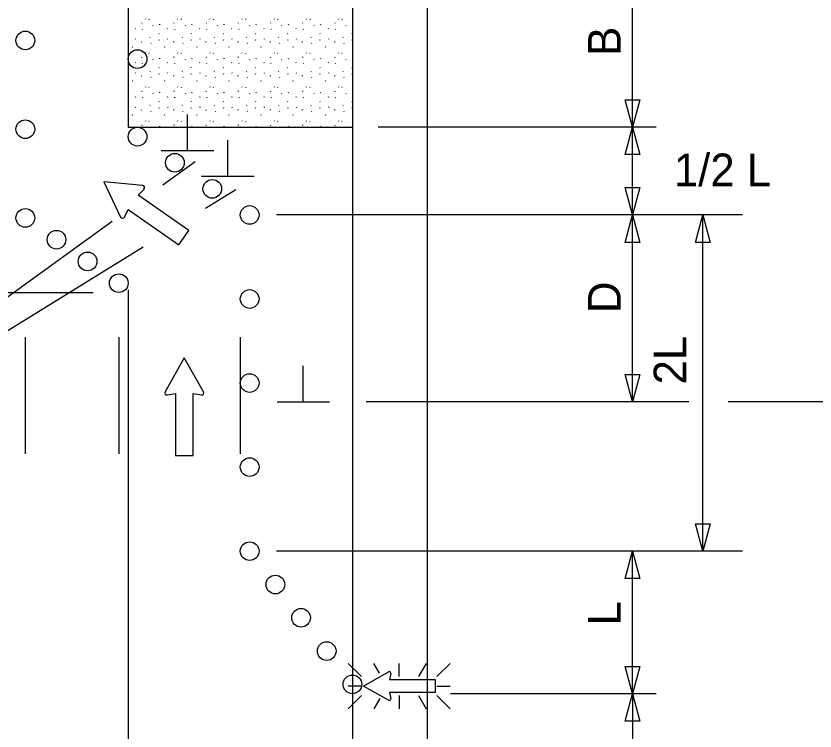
# Model space of a CAD drawing. Extents: x 16525 to 18478, y 5730 to 6927.
# Drawn here: x 17075.6 to 17246.6, y 6369.8 to 6523 of the extents above; entities that cross this region are included whole.
import ezdxf

# ---------------------------------------------------------------- set-up
doc = ezdxf.new("R2010")
doc.units = 0
for name, color, linetype in [('ALI_LEGAL_EX', 7, 'Continuous'), ('MT_SCRATCH_LEVEL_A', 7, 'Continuous'), ('MT_SCRATCH_LEVEL_E', 7, 'Continuous'), ('PAVT_EDGE_EX', 7, 'Continuous'), ('TRAFFIC_SIGNS_PR', 7, 'Continuous'), ('TYPICAL_TEXT_DIMEN_PR', 7, 'Continuous')]:
    doc.layers.add(name, color=color, linetype=linetype)

msp = doc.modelspace()

# ---------------------------------------------------------------- linework, layer by layer
at = {"layer": 'ALI_LEGAL_EX'}
for points in [[(17077.59, 6454.22), (17077.59, 6429.22)], [(17097.59, 6454.22), (17097.59, 6429.22)], [(17123.59, 6454.22), (17123.59, 6429.22)]]:
    msp.add_lwpolyline(points, dxfattribs=at)
at = {"layer": 'MT_SCRATCH_LEVEL_A'}
for p, q in [((17103.3, 6522.35), (17103.35, 6522.27)), ((17104.04, 6522.32), (17104.09, 6522.24)), ((17110.19, 6522.35), (17110.24, 6522.27)), ((17110.92, 6522.32), (17110.98, 6522.24)), ((17117.07, 6522.35), (17117.13, 6522.27)), ((17117.81, 6522.32), (17117.86, 6522.24)), ((17123.96, 6522.35), (17124.01, 6522.27)), ((17124.7, 6522.32), (17124.75, 6522.24)), ((17130.85, 6522.35), (17130.9, 6522.27)), ((17131.59, 6522.32), (17131.64, 6522.24)), ((17137.74, 6522.35), (17137.79, 6522.27)), ((17138.47, 6522.32), (17138.53, 6522.24)), ((17144.62, 6522.35), (17144.68, 6522.27)), ((17145.36, 6522.32), (17145.41, 6522.24)), ((17101.08, 6520.26), (17101.14, 6520.18)), ((17102.53, 6521.39), (17102.59, 6521.5)), ((17102.62, 6520.12), (17102.67, 6520.04)), ((17104.9, 6520.94), (17104.96, 6520.86)), ((17106.35, 6521.09), (17106.41, 6521.21)), ((17107.97, 6520.26), (17108.02, 6520.18)), ((17109.42, 6521.39), (17109.47, 6521.5)), ((17109.5, 6520.12), (17109.55, 6520.04)), ((17111.79, 6520.94), (17111.84, 6520.86)), ((17113.24, 6521.09), (17113.29, 6521.21)), ((17114.86, 6520.26), (17114.91, 6520.18)), ((17116.31, 6521.39), (17116.36, 6521.5)), ((17116.39, 6520.12), (17116.44, 6520.04)), ((17118.68, 6520.94), (17118.73, 6520.86)), ((17120.13, 6521.09), (17120.18, 6521.21)), ((17121.75, 6520.26), (17121.8, 6520.18)), ((17123.2, 6521.39), (17123.25, 6521.5)), ((17123.28, 6520.12), (17123.33, 6520.04)), ((17125.57, 6520.94), (17125.62, 6520.86)), ((17127.02, 6521.09), (17127.07, 6521.21)), ((17128.64, 6520.26), (17128.69, 6520.18)), ((17130.08, 6521.39), (17130.14, 6521.5)), ((17130.17, 6520.12), (17130.22, 6520.04)), ((17132.46, 6520.94), (17132.51, 6520.86)), ((17133.9, 6521.09), (17133.96, 6521.21)), ((17135.52, 6520.26), (17135.57, 6520.18)), ((17136.97, 6521.39), (17137.02, 6521.5)), ((17137.05, 6520.12), (17137.1, 6520.04)), ((17139.34, 6520.94), (17139.39, 6520.86)), ((17140.79, 6521.09), (17140.84, 6521.21)), ((17142.41, 6520.26), (17142.46, 6520.18)), ((17143.86, 6521.39), (17143.91, 6521.5)), ((17143.94, 6520.12), (17143.99, 6520.04)), ((17146.23, 6520.94), (17146.28, 6520.86)), ((17104.26, 6518.33), (17104.31, 6518.45)), ((17106.18, 6519.2), (17106.23, 6519.12)), ((17111.14, 6518.33), (17111.2, 6518.45)), ((17113.07, 6519.2), (17113.12, 6519.12)), ((17118.03, 6518.33), (17118.08, 6518.45)), ((17119.96, 6519.2), (17120.01, 6519.12)), ((17124.92, 6518.33), (17124.97, 6518.45)), ((17126.85, 6519.2), (17126.9, 6519.12)), ((17131.81, 6518.33), (17131.86, 6518.45)), ((17133.73, 6519.2), (17133.78, 6519.12)), ((17138.69, 6518.33), (17138.75, 6518.45)), ((17140.62, 6519.2), (17140.67, 6519.12)), ((17145.58, 6518.33), (17145.63, 6518.45)), ((17147.51, 6519.2), (17147.56, 6519.12)), ((17101.13, 6518.05), (17101.19, 6517.97)), ((17102.42, 6517.48), (17102.43, 6517.36)), ((17104.44, 6517.13), (17104.5, 6517.06)), ((17106.22, 6517.8), (17106.28, 6517.92)), ((17108.02, 6518.05), (17108.07, 6517.97)), ((17109.3, 6517.48), (17109.32, 6517.36)), ((17111.33, 6517.13), (17111.38, 6517.06)), ((17113.11, 6517.8), (17113.16, 6517.92)), ((17114.91, 6518.05), (17114.96, 6517.97)), ((17116.19, 6517.48), (17116.2, 6517.36)), ((17118.22, 6517.13), (17118.27, 6517.06)), ((17120, 6517.8), (17120.05, 6517.92)), ((17121.8, 6518.05), (17121.85, 6517.97)), ((17123.08, 6517.48), (17123.09, 6517.36)), ((17125.11, 6517.13), (17125.16, 6517.06)), ((17126.89, 6517.8), (17126.94, 6517.92)), ((17128.68, 6518.05), (17128.74, 6517.97)), ((17129.97, 6517.48), (17129.98, 6517.36)), ((17131.99, 6517.13), (17132.05, 6517.06)), ((17133.78, 6517.8), (17133.83, 6517.92)), ((17135.57, 6518.05), (17135.62, 6517.97)), ((17136.85, 6517.48), (17136.87, 6517.36)), ((17138.88, 6517.13), (17138.93, 6517.06)), ((17140.66, 6517.8), (17140.71, 6517.92)), ((17142.46, 6518.05), (17142.51, 6517.97)), ((17143.74, 6517.48), (17143.75, 6517.36)), ((17145.77, 6517.13), (17145.82, 6517.06)), ((17147.55, 6517.8), (17147.6, 6517.92)), ((17100.51, 6516.3), (17100.57, 6516.42)), ((17103.3, 6515.06), (17103.35, 6514.99)), ((17104.04, 6515.03), (17104.09, 6514.95)), ((17107.4, 6516.3), (17107.46, 6516.42)), ((17110.19, 6515.06), (17110.24, 6514.99)), ((17110.92, 6515.03), (17110.98, 6514.95)), ((17114.29, 6516.3), (17114.34, 6516.42)), ((17117.07, 6515.06), (17117.13, 6514.99)), ((17117.81, 6515.03), (17117.86, 6514.95)), ((17121.18, 6516.3), (17121.23, 6516.42)), ((17123.96, 6515.06), (17124.01, 6514.99)), ((17124.7, 6515.03), (17124.75, 6514.95)), ((17128.06, 6516.3), (17128.12, 6516.42)), ((17130.85, 6515.06), (17130.9, 6514.99)), ((17131.59, 6515.03), (17131.64, 6514.95)), ((17134.95, 6516.3), (17135.01, 6516.42)), ((17137.74, 6515.06), (17137.79, 6514.99)), ((17138.47, 6515.03), (17138.53, 6514.95)), ((17141.84, 6516.3), (17141.89, 6516.42)), ((17144.62, 6515.06), (17144.68, 6514.99)), ((17145.36, 6515.03), (17145.41, 6514.95)), ((17102.53, 6514.1), (17102.59, 6514.22)), ((17104.9, 6513.65), (17104.96, 6513.58)), ((17106.35, 6513.81), (17106.41, 6513.92)), ((17109.42, 6514.1), (17109.47, 6514.22)), ((17111.79, 6513.65), (17111.84, 6513.58)), ((17113.24, 6513.81), (17113.29, 6513.92)), ((17116.31, 6514.1), (17116.36, 6514.22)), ((17118.68, 6513.65), (17118.73, 6513.58)), ((17120.13, 6513.81), (17120.18, 6513.92)), ((17123.2, 6514.1), (17123.25, 6514.22)), ((17125.57, 6513.65), (17125.62, 6513.58)), ((17127.02, 6513.81), (17127.07, 6513.92)), ((17130.08, 6514.1), (17130.14, 6514.22)), ((17132.46, 6513.65), (17132.51, 6513.58)), ((17133.9, 6513.81), (17133.96, 6513.92)), ((17136.97, 6514.1), (17137.02, 6514.22)), ((17139.34, 6513.65), (17139.39, 6513.58)), ((17140.79, 6513.81), (17140.84, 6513.92)), ((17143.86, 6514.1), (17143.91, 6514.22)), ((17146.23, 6513.65), (17146.28, 6513.58)), ((17101.08, 6512.98), (17101.14, 6512.9)), ((17102.62, 6512.84), (17102.67, 6512.76)), ((17106.18, 6511.92), (17106.23, 6511.84)), ((17107.97, 6512.98), (17108.02, 6512.9)), ((17109.5, 6512.84), (17109.55, 6512.76)), ((17113.07, 6511.92), (17113.12, 6511.84)), ((17114.86, 6512.98), (17114.91, 6512.9)), ((17116.39, 6512.84), (17116.44, 6512.76)), ((17119.96, 6511.92), (17120.01, 6511.84)), ((17121.75, 6512.98), (17121.8, 6512.9)), ((17123.28, 6512.84), (17123.33, 6512.76)), ((17126.85, 6511.92), (17126.9, 6511.84)), ((17128.64, 6512.98), (17128.69, 6512.9)), ((17130.17, 6512.84), (17130.22, 6512.76)), ((17133.73, 6511.92), (17133.78, 6511.84)), ((17135.52, 6512.98), (17135.57, 6512.9)), ((17137.05, 6512.84), (17137.1, 6512.76)), ((17140.62, 6511.92), (17140.67, 6511.84)), ((17142.41, 6512.98), (17142.46, 6512.9)), ((17143.94, 6512.84), (17143.99, 6512.76)), ((17147.51, 6511.92), (17147.56, 6511.84)), ((17101.13, 6510.77), (17101.19, 6510.69)), ((17102.42, 6510.19), (17102.43, 6510.07)), ((17104.26, 6511.05), (17104.31, 6511.16)), ((17104.44, 6509.85), (17104.5, 6509.77)), ((17106.22, 6510.52), (17106.28, 6510.63)), ((17108.02, 6510.77), (17108.07, 6510.69)), ((17109.3, 6510.19), (17109.32, 6510.07)), ((17111.14, 6511.05), (17111.2, 6511.16)), ((17111.33, 6509.85), (17111.38, 6509.77)), ((17113.11, 6510.52), (17113.16, 6510.63)), ((17114.91, 6510.77), (17114.96, 6510.69)), ((17116.19, 6510.19), (17116.2, 6510.07)), ((17118.03, 6511.05), (17118.08, 6511.16)), ((17118.22, 6509.85), (17118.27, 6509.77)), ((17120, 6510.52), (17120.05, 6510.63)), ((17121.8, 6510.77), (17121.85, 6510.69)), ((17123.08, 6510.19), (17123.09, 6510.07)), ((17124.92, 6511.05), (17124.97, 6511.16)), ((17125.11, 6509.85), (17125.16, 6509.77)), ((17126.89, 6510.52), (17126.94, 6510.63)), ((17128.68, 6510.77), (17128.74, 6510.69)), ((17129.97, 6510.19), (17129.98, 6510.07)), ((17131.81, 6511.05), (17131.86, 6511.16)), ((17131.99, 6509.85), (17132.05, 6509.77)), ((17133.78, 6510.52), (17133.83, 6510.63)), ((17135.57, 6510.77), (17135.62, 6510.69)), ((17136.85, 6510.19), (17136.87, 6510.07)), ((17138.69, 6511.05), (17138.75, 6511.16)), ((17138.88, 6509.85), (17138.93, 6509.77)), ((17140.66, 6510.52), (17140.71, 6510.63)), ((17142.46, 6510.77), (17142.51, 6510.69)), ((17143.74, 6510.19), (17143.75, 6510.07)), ((17145.58, 6511.05), (17145.63, 6511.16)), ((17145.77, 6509.85), (17145.82, 6509.77)), ((17147.55, 6510.52), (17147.6, 6510.63)), ((17100.51, 6509.01), (17100.57, 6509.13)), ((17107.4, 6509.01), (17107.46, 6509.13)), ((17114.29, 6509.01), (17114.34, 6509.13)), ((17121.18, 6509.01), (17121.23, 6509.13)), ((17128.06, 6509.01), (17128.12, 6509.13)), ((17134.95, 6509.01), (17135.01, 6509.13)), ((17141.84, 6509.01), (17141.89, 6509.13)), ((17102.53, 6506.82), (17102.59, 6506.93)), ((17103.3, 6507.78), (17103.35, 6507.7)), ((17104.04, 6507.75), (17104.09, 6507.67)), ((17104.9, 6506.37), (17104.96, 6506.29)), ((17106.35, 6506.52), (17106.41, 6506.64)), ((17109.42, 6506.82), (17109.47, 6506.93)), ((17110.19, 6507.78), (17110.24, 6507.7)), ((17110.92, 6507.75), (17110.98, 6507.67)), ((17111.79, 6506.37), (17111.84, 6506.29)), ((17113.24, 6506.52), (17113.29, 6506.64)), ((17116.31, 6506.82), (17116.36, 6506.93)), ((17117.07, 6507.78), (17117.13, 6507.7)), ((17117.81, 6507.75), (17117.86, 6507.67)), ((17118.68, 6506.37), (17118.73, 6506.29)), ((17120.13, 6506.52), (17120.18, 6506.64)), ((17123.2, 6506.82), (17123.25, 6506.93)), ((17123.96, 6507.78), (17124.01, 6507.7)), ((17124.7, 6507.75), (17124.75, 6507.67)), ((17125.57, 6506.37), (17125.62, 6506.29)), ((17127.02, 6506.52), (17127.07, 6506.64)), ((17130.08, 6506.82), (17130.14, 6506.93)), ((17130.85, 6507.78), (17130.9, 6507.7)), ((17131.59, 6507.75), (17131.64, 6507.67)), ((17132.46, 6506.37), (17132.51, 6506.29)), ((17133.9, 6506.52), (17133.96, 6506.64)), ((17136.97, 6506.82), (17137.02, 6506.93)), ((17137.74, 6507.78), (17137.79, 6507.7)), ((17138.47, 6507.75), (17138.53, 6507.67)), ((17139.34, 6506.37), (17139.39, 6506.29)), ((17140.79, 6506.52), (17140.84, 6506.64)), ((17143.86, 6506.82), (17143.91, 6506.93)), ((17144.62, 6507.78), (17144.68, 6507.7)), ((17145.36, 6507.75), (17145.41, 6507.67)), ((17146.23, 6506.37), (17146.28, 6506.29)), ((17101.08, 6505.69), (17101.14, 6505.61)), ((17102.62, 6505.55), (17102.67, 6505.47)), ((17106.18, 6504.63), (17106.23, 6504.55)), ((17107.97, 6505.69), (17108.02, 6505.61)), ((17109.5, 6505.55), (17109.55, 6505.47)), ((17113.07, 6504.63), (17113.12, 6504.55)), ((17114.86, 6505.69), (17114.91, 6505.61)), ((17116.39, 6505.55), (17116.44, 6505.47)), ((17119.96, 6504.63), (17120.01, 6504.55)), ((17121.75, 6505.69), (17121.8, 6505.61)), ((17123.28, 6505.55), (17123.33, 6505.47)), ((17126.85, 6504.63), (17126.9, 6504.55)), ((17128.64, 6505.69), (17128.69, 6505.61)), ((17130.17, 6505.55), (17130.22, 6505.47)), ((17133.73, 6504.63), (17133.78, 6504.55)), ((17135.52, 6505.69), (17135.57, 6505.61)), ((17137.05, 6505.55), (17137.1, 6505.47)), ((17140.62, 6504.63), (17140.67, 6504.55)), ((17142.41, 6505.69), (17142.46, 6505.61)), ((17143.94, 6505.55), (17143.99, 6505.47)), ((17147.51, 6504.63), (17147.56, 6504.55)), ((17101.13, 6503.48), (17101.19, 6503.4)), ((17104.26, 6503.76), (17104.31, 6503.88)), ((17106.22, 6503.23), (17106.28, 6503.35)), ((17108.02, 6503.48), (17108.07, 6503.4)), ((17111.14, 6503.76), (17111.2, 6503.88)), ((17113.11, 6503.23), (17113.16, 6503.35)), ((17114.91, 6503.48), (17114.96, 6503.4)), ((17118.03, 6503.76), (17118.08, 6503.88)), ((17120, 6503.23), (17120.05, 6503.35)), ((17121.8, 6503.48), (17121.85, 6503.4)), ((17124.92, 6503.76), (17124.97, 6503.88)), ((17126.89, 6503.23), (17126.94, 6503.35)), ((17128.68, 6503.48), (17128.74, 6503.4)), ((17131.81, 6503.76), (17131.86, 6503.88)), ((17133.78, 6503.23), (17133.83, 6503.35)), ((17135.57, 6503.48), (17135.62, 6503.4)), ((17138.69, 6503.76), (17138.75, 6503.88)), ((17140.66, 6503.23), (17140.71, 6503.35)), ((17142.46, 6503.48), (17142.51, 6503.4)), ((17145.58, 6503.76), (17145.63, 6503.88)), ((17147.55, 6503.23), (17147.6, 6503.35)), ((17100.51, 6501.73), (17100.57, 6501.85)), ((17102.42, 6502.91), (17102.43, 6502.79)), ((17104.44, 6502.56), (17104.5, 6502.49)), ((17107.4, 6501.73), (17107.46, 6501.85)), ((17109.3, 6502.91), (17109.32, 6502.79)), ((17111.33, 6502.56), (17111.38, 6502.49)), ((17114.29, 6501.73), (17114.34, 6501.85)), ((17116.19, 6502.91), (17116.2, 6502.79)), ((17118.22, 6502.56), (17118.27, 6502.49)), ((17121.18, 6501.73), (17121.23, 6501.85)), ((17123.08, 6502.91), (17123.09, 6502.79)), ((17125.11, 6502.56), (17125.16, 6502.49)), ((17128.06, 6501.73), (17128.12, 6501.85)), ((17129.97, 6502.91), (17129.98, 6502.79)), ((17131.99, 6502.56), (17132.05, 6502.49)), ((17134.95, 6501.73), (17135.01, 6501.85)), ((17136.85, 6502.91), (17136.87, 6502.79)), ((17138.88, 6502.56), (17138.93, 6502.49)), ((17141.84, 6501.73), (17141.89, 6501.85)), ((17143.74, 6502.91), (17143.75, 6502.79)), ((17145.77, 6502.56), (17145.82, 6502.49)), ((17102.53, 6499.53), (17102.59, 6499.65)), ((17103.3, 6500.49), (17103.35, 6500.41)), ((17104.04, 6500.46), (17104.09, 6500.39)), ((17109.42, 6499.53), (17109.47, 6499.65)), ((17110.19, 6500.49), (17110.24, 6500.41)), ((17110.92, 6500.46), (17110.98, 6500.39)), ((17116.31, 6499.53), (17116.36, 6499.65)), ((17117.07, 6500.49), (17117.13, 6500.41)), ((17117.81, 6500.46), (17117.86, 6500.39)), ((17123.2, 6499.53), (17123.25, 6499.65)), ((17123.96, 6500.49), (17124.01, 6500.41)), ((17124.7, 6500.46), (17124.75, 6500.39)), ((17130.08, 6499.53), (17130.14, 6499.65)), ((17130.85, 6500.49), (17130.9, 6500.41)), ((17131.59, 6500.46), (17131.64, 6500.39)), ((17136.97, 6499.53), (17137.02, 6499.65)), ((17137.74, 6500.49), (17137.79, 6500.41)), ((17138.47, 6500.46), (17138.53, 6500.39)), ((17143.86, 6499.53), (17143.91, 6499.65)), ((17144.62, 6500.49), (17144.68, 6500.41)), ((17145.36, 6500.46), (17145.41, 6500.39)), ((17099.59, 6499.17), (17147.59, 6499.17)), ((17106.35, 6499.24), (17106.41, 6499.35)), ((17113.24, 6499.24), (17113.29, 6499.35)), ((17120.13, 6499.24), (17120.18, 6499.35)), ((17127.02, 6499.24), (17127.07, 6499.35)), ((17133.9, 6499.24), (17133.96, 6499.35)), ((17140.79, 6499.24), (17140.84, 6499.35))]:
    msp.add_line(p, q, dxfattribs=at)
at = {"layer": 'MT_SCRATCH_LEVEL_E'}
for p, q in [((17094.4, 6487.42), (17097.98, 6479.91)), ((17102.71, 6486.68), (17094.4, 6487.42)), ((17094.4, 6487.42), (17097.98, 6479.91)), ((17102.71, 6486.68), (17094.4, 6487.42)), ((17101.72, 6484.61), (17103, 6485.89)), ((17101.72, 6484.61), (17103, 6485.89)), ((17112.59, 6477.02), (17101.72, 6484.61)), ((17112.59, 6477.02), (17101.72, 6484.61)), ((17098.82, 6479.91), (17099.58, 6481.55)), ((17098.82, 6479.91), (17099.58, 6481.55)), ((17099.58, 6481.55), (17110.45, 6473.96)), ((17099.58, 6481.55), (17110.45, 6473.96)), ((17110.45, 6473.96), (17112.59, 6477.02)), ((17110.45, 6473.96), (17112.59, 6477.02)), ((17111.61, 6449.74), (17107.5, 6442.5)), ((17111.61, 6449.74), (17107.5, 6442.5)), ((17115.76, 6442.5), (17111.61, 6449.74)), ((17115.76, 6442.5), (17111.61, 6449.74)), ((17107.99, 6441.82), (17109.76, 6442.13)), ((17107.99, 6441.82), (17109.76, 6442.13)), ((17109.76, 6442.13), (17109.76, 6428.88)), ((17109.76, 6442.13), (17109.76, 6428.88)), ((17113.5, 6428.88), (17113.5, 6442.13)), ((17113.5, 6442.13), (17115.28, 6441.82)), ((17113.5, 6428.88), (17113.5, 6442.13)), ((17113.5, 6442.13), (17115.28, 6441.82)), ((17109.76, 6428.88), (17113.5, 6428.88)), ((17109.76, 6428.88), (17113.5, 6428.88))]:
    msp.add_line(p, q, dxfattribs=at)
for centre, start, end in [((17102.66, 6486.21), 315.105, 84.8419), ((17102.66, 6486.21), 315.105, 84.8419), ((17098.4, 6480.11), 205.4936, 335.0326), ((17098.4, 6480.11), 205.4936, 335.0326), ((17107.91, 6442.28), 150.4248, 279.9638), ((17107.91, 6442.28), 150.4248, 279.9638), ((17115.35, 6442.28), 260.0362, 29.7731), ((17115.35, 6442.28), 260.0362, 29.7731)]:
    msp.add_arc(centre, 0.463, start, end, dxfattribs=at)
at = {"layer": 'PAVT_EDGE_EX'}
for p, q in [((17147.59, 6917.57), (17147.59, 6063.18)), ((17163.59, 6917.57), (17163.59, 6063.18)), ((17099.59, 6651.4), (17099.59, 6499.17)), ((17099.59, 6464.33), (17099.59, 6063.18))]:
    msp.add_line(p, q, dxfattribs=at)
at = {"layer": 'TRAFFIC_SIGNS_PR'}
for p, q in [((17146.72, 6384.32), (17149.54, 6381.51)), ((17152.15, 6384.33), (17153.36, 6382.23)), ((17157.62, 6381.51), (17157.62, 6384.33)), ((17163.41, 6384.33), (17161.78, 6381.51)), ((17165.71, 6381.51), (17168.53, 6384.33)), ((17149.54, 6379.47), (17146.72, 6379.47)), ((17165.71, 6379.47), (17168.53, 6379.47)), ((17146.72, 6374.62), (17149.54, 6377.44)), ((17153.44, 6376.81), (17152.18, 6374.62)), ((17157.62, 6377.44), (17157.62, 6374.62)), ((17161.76, 6377.44), (17163.39, 6374.62)), ((17165.71, 6377.44), (17168.53, 6374.62))]:
    msp.add_line(p, q, dxfattribs=at)
for points in [[(17155.3, 6376.46), (17149.99, 6379.47), (17155.3, 6382.52)], [(17155.8, 6382.16), (17155.57, 6380.86), (17165.29, 6380.86), (17165.29, 6378.12), (17155.57, 6378.12), (17155.8, 6376.81)]]:
    msp.add_lwpolyline(points, dxfattribs=at)
for centre in [(17077.59, 6517.72), (17101.61, 6513.73), (17077.59, 6498.72), (17101.61, 6497.12), (17101.61, 6497.12), (17101.61, 6497.12), (17109.61, 6491.53), (17117.61, 6485.94), (17077.59, 6479.72), (17125.61, 6480.36), (17084.26, 6475.06), (17090.92, 6470.41), (17097.59, 6465.75), (17125.61, 6462.36), (17125.61, 6444.36), (17125.61, 6426.36), (17125.61, 6408.36), (17131.11, 6401.22), (17136.61, 6394.1), (17142.1, 6386.97), (17147.6, 6379.84)]:
    msp.add_circle(centre, 2, dxfattribs=at)
for centre, start, end in [((17155.46, 6382.22), 350.0407, 118.5167), ((17155.46, 6376.76), 241.1084, 9.2692)]:
    msp.add_arc(centre, 0.341, start, end, dxfattribs=at)
at = {"layer": 'TYPICAL_TEXT_DIMEN_PR'}
for p, q in [((17207.59, 6499.17), (17207.59, 6531.23)), ((17207.59, 6499.17), (17206.02, 6505.03)), ((17206.02, 6505.03), (17207.59, 6505.03)), ((17207.59, 6505.03), (17209.16, 6505.03)), ((17209.16, 6505.03), (17207.59, 6499.17)), ((17112.33, 6494.1), (17112.33, 6501.89)), ((17212.59, 6499.17), (17153.09, 6499.17)), ((17206.02, 6493.31), (17207.59, 6499.17)), ((17207.59, 6499.17), (17209.16, 6493.31)), ((17207.59, 6480.36), (17207.59, 6499.17)), ((17120.92, 6488.59), (17120.92, 6496.37)), ((17117.95, 6494.1), (17106.7, 6494.1)), ((17207.59, 6493.31), (17206.02, 6493.31)), ((17209.16, 6493.31), (17207.59, 6493.31)), ((17107.02, 6486.83), (17113.94, 6491.82)), ((17126.55, 6488.59), (17115.3, 6488.59)), ((17207.59, 6480.36), (17206.02, 6486.22)), ((17206.02, 6486.22), (17207.59, 6486.22)), ((17207.59, 6486.22), (17209.16, 6486.22)), ((17209.16, 6486.22), (17207.59, 6480.36)), ((17116.19, 6481.78), (17122.68, 6485.78)), ((17003.97, 6412.5), (17096.17, 6479.01)), ((17231.08, 6480.36), (17131.36, 6480.36)), ((17206.02, 6474.49), (17207.59, 6480.36)), ((17207.59, 6440.36), (17207.59, 6480.36)), ((17207.59, 6480.36), (17209.16, 6474.49)), ((17221.02, 6474.49), (17222.59, 6480.36)), ((17222.59, 6408.36), (17222.59, 6480.36)), ((17222.59, 6480.36), (17224.16, 6474.49)), ((17207.59, 6474.49), (17206.02, 6474.49)), ((17209.16, 6474.49), (17207.59, 6474.49)), ((17222.59, 6474.49), (17221.02, 6474.49)), ((17224.16, 6474.49), (17222.59, 6474.49)), ((17003.97, 6412.5), (17102.79, 6473.5)), ((16962.49, 6463.75), (17092.12, 6463.75)), ((17137.09, 6440.28), (17137.09, 6448.06)), ((17207.59, 6440.36), (17206.02, 6446.22)), ((17206.02, 6446.22), (17207.59, 6446.22)), ((17207.59, 6446.22), (17209.16, 6446.22)), ((17209.16, 6446.22), (17207.59, 6440.36)), ((17142.72, 6440.28), (17131.47, 6440.28)), ((17219.61, 6440.36), (17150.56, 6440.36)), ((17276.02, 6440.36), (17228.05, 6440.36)), ((17222.59, 6408.36), (17221.02, 6414.22)), ((17221.02, 6414.22), (17222.59, 6414.22)), ((17222.59, 6414.22), (17224.16, 6414.22)), ((17224.16, 6414.22), (17222.59, 6408.36)), ((17231.08, 6408.36), (17131.36, 6408.36)), ((17206.02, 6402.49), (17207.59, 6408.36)), ((17207.59, 6377.84), (17207.59, 6408.36)), ((17207.59, 6408.36), (17209.16, 6402.49)), ((17207.59, 6402.49), (17206.02, 6402.49)), ((17209.16, 6402.49), (17207.59, 6402.49)), ((17207.59, 6377.84), (17206.02, 6383.7)), ((17206.02, 6383.7), (17207.59, 6383.7)), ((17207.59, 6383.7), (17209.16, 6383.7)), ((17209.16, 6383.7), (17207.59, 6377.84)), ((17212.59, 6377.84), (17168.6, 6377.84)), ((17206.02, 6371.98), (17207.59, 6377.84)), ((17207.59, 6377.84), (17207.59, 6337.84)), ((17207.59, 6377.84), (17209.16, 6371.98)), ((17207.59, 6371.98), (17206.02, 6371.98)), ((17209.16, 6371.98), (17207.59, 6371.98))]:
    msp.add_line(p, q, dxfattribs=at)

# ---------------------------------------------------------------- texts
for s, p in [('B', (17205.03, 6514.43)), ('D', (17205.03, 6459.34)), ('2L', (17219.09, 6444.06)), ('L', (17205.03, 6392.46))]:
    msp.add_text(s, height=7, rotation=90, dxfattribs=at).set_placement(p)
msp.add_text('1/2 L', height=7, dxfattribs=at).set_placement((17216.41, 6486.5))

doc.saveas('drawing.dxf')
